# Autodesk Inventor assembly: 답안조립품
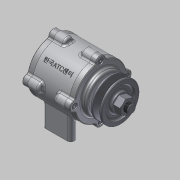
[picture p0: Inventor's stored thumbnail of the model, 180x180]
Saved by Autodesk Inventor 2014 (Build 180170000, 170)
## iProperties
Created: 2015-03
Part Number: 답안조립품
Document SubType Name: Weldment
Designer: Administrator
Weld Material: Welded Aluminum-6061
Author: Administrator
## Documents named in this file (11)
- C:\Documents and Settings\Administrator\바탕 화면\450306V1010\답안조립품.iam
- C:\Documents and Settings\Administrator\바탕 화면\450306V1010\본체.ipt
- C:\Documents and Settings\Administrator\바탕 화면\450306V1010\축.ipt
- C:\Documents and Settings\Administrator\바탕 화면\450306V1010\베어링 6204.ipt
- C:\Documents and Settings\Administrator\바탕 화면\450306V1010\키(4 x 4 x 12).ipt
- C:\Documents and Settings\Administrator\바탕 화면\450306V1010\커버2.ipt
- C:\Documents and Settings\Administrator\바탕 화면\450306V1010\M 4 x 12.ipt
- C:\Documents and Settings\Administrator\바탕 화면\450306V1010\커버.ipt
- C:\Documents and Settings\Administrator\바탕 화면\450306V1010\V벨트풀리.ipt
- C:\Documents and Settings\Administrator\바탕 화면\450306V1010\오일실.ipt
- C:\Documents and Settings\Administrator\바탕 화면\450306V1010\너트 M12x1.25.ipt
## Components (14 placed, 6 different names)
1. KS B 2023 6204 - 20 x 47 x 14:1 — 각도:1
2. KS B 2023 6204 - 20 x 47 x 14:2 — 각도:2
3. KS B 1311 (I) 4 x 4 x 12:1
4. 그루브 풀리1:1
5. KS B 2804 D D - 20 32 8:1
6. KS B 1012 클래스 1 일반 - 미터 M12x1.25:1 — 각도:3
7. KS B 1003 - 미터 M 4 x 12:1
8. KS B 1003 - 미터 M 4 x 12:2
9. KS B 1003 - 미터 M 4 x 12:3
10. KS B 1003 - 미터 M 4 x 12:4
11. KS B 1003 - 미터 M 4 x 12:5
12. KS B 1003 - 미터 M 4 x 12:6
13. KS B 1003 - 미터 M 4 x 12:7
14. KS B 1003 - 미터 M 4 x 12:8
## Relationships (3: Angle 3)
- 각도:1 [Angle]: KS B 2023 6204 - 20 x 47 x 14:1
- 각도:2 [Angle]: KS B 2023 6204 - 20 x 47 x 14:2
- 각도:3 [Angle]: KS B 1012 클래스 1 일반 - 미터 M12x1.25:1
